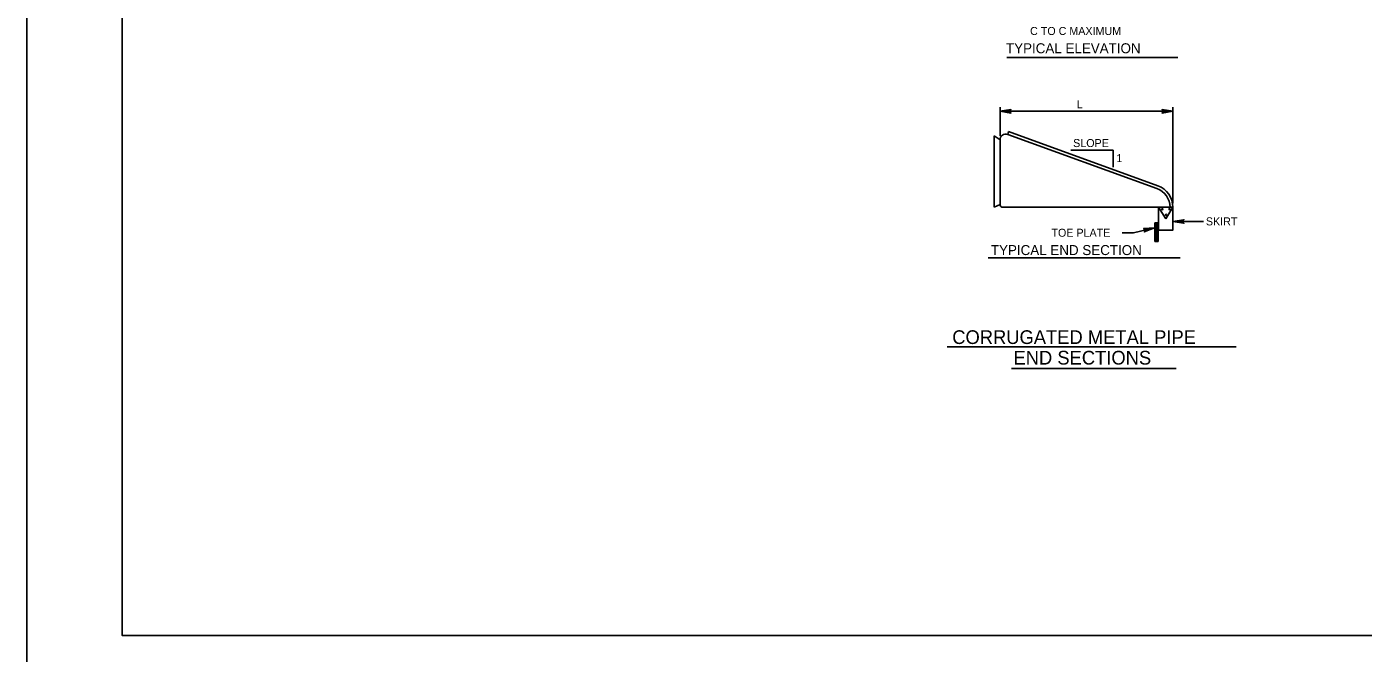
# Model space of a CAD drawing. Extents: x -17 to 888, y -473 to 715.
# Drawn here: x -17 to 544, y 128 to 392 of the extents above; entities that cross this region are included whole.
import ezdxf

# ---------------------------------------------------------------- set-up
doc = ezdxf.new("R2010")
doc.units = 0
for name, color, linetype in [('1', 7, 'Continuous'), ('2', 7, 'Continuous'), ('3', 7, 'Continuous'), ('PLT-BNDY', 7, 'Continuous')]:
    doc.layers.add(name, color=color, linetype=linetype)

msp = doc.modelspace()

# ---------------------------------------------------------------- linework, layer by layer
at = {"layer": '1'}
for p, q in [((456.24, 309.26), (457.69, 309.26)), ((456.24, 308.39), (457.69, 308.39)), ((456.24, 307.46), (457.69, 307.46)), ((456.24, 306.53), (457.69, 306.53)), ((456.24, 305.39), (457.69, 305.39)), ((456.24, 304.46), (457.69, 304.46)), ((456.24, 303.43), (457.69, 303.43)), ((456.24, 302.4), (457.69, 302.4)), ((456.24, 301.47), (457.69, 301.47))]:
    msp.add_line(p, q, dxfattribs=at)
msp.add_lwpolyline([(808.79, 135.89), (808.79, 699.89), (22.79, 699.89), (22.79, 135.89), (808.79, 135.89), (808.79, 162.25), (608.79, 162.25), (608.79, 226.93), (808.79, 226.93), (808.79, 255.89), (608.79, 255.89), (608.79, 135.89), (687.6, 135.89), (687.6, 162.25), (687.6, 135.89), (764.6, 135.89), (764.6, 162.25), (764.6, 149.93), (808.79, 149.93)], dxfattribs=at)
at = {"layer": '2'}
for p, q in [((391.29, 345.86), (391.29, 357.8)), ((436.88, 356.12), (391.29, 356.12)), ((463.87, 356.12), (436.88, 356.12)), ((463.87, 317.48), (463.87, 357.8)), ((388.89, 345.8), (388.89, 315.8)), ((388.89, 345.8), (391.29, 344.18)), ((391.29, 344.18), (391.29, 317)), ((394.92, 347.56), (394.51, 346.43)), ((394.51, 346.43), (457.14, 323.7)), ((394.92, 347.56), (457.55, 324.82)), ((438.84, 339.82), (421.04, 339.82)), ((438.84, 332.62), (438.84, 339.82)), ((388.89, 315.8), (391.29, 317)), ((392.49, 315.8), (462.67, 315.8)), ((457.87, 315.8), (460.87, 311)), ((459.19, 315.01), (459.41, 315.18)), ((459.41, 315.18), (459.19, 314.89)), ((459.19, 314.89), (459.59, 315.02)), ((459.27, 314.81), (459.19, 315.01)), ((459.37, 314.79), (459.26, 315.14)), ((459.26, 315.14), (459.27, 314.81)), ((459.59, 315.02), (459.33, 314.78)), ((459.33, 314.78), (459.56, 314.85)), ((459.42, 314.83), (459.36, 315.18)), ((459.36, 315.18), (459.37, 314.79)), ((459.39, 314.98), (459.39, 314.98)), ((459.44, 315.17), (459.42, 314.83)), ((459.54, 314.89), (459.44, 315.17)), ((459.54, 315.12), (459.54, 314.89)), ((463.87, 315.8), (460.87, 311)), ((462.21, 315.03), (462.43, 315.2)), ((462.43, 315.2), (462.21, 314.9)), ((462.21, 314.9), (462.6, 315.04)), ((462.28, 314.83), (462.21, 315.03)), ((462.38, 314.8), (462.28, 315.15)), ((462.28, 315.15), (462.28, 314.83)), ((462.6, 315.04), (462.34, 314.8)), ((462.34, 314.8), (462.58, 314.87)), ((462.44, 314.84), (462.37, 315.2)), ((462.37, 315.2), (462.38, 314.8)), ((462.4, 315), (462.4, 315)), ((462.46, 315.18), (462.44, 314.84)), ((462.55, 314.91), (462.46, 315.18)), ((462.55, 315.13), (462.55, 314.91)), ((462.67, 315.8), (463.87, 315.8)), ((456.24, 309.26), (456.24, 301.47)), ((456.73, 309.26), (456.73, 301.47)), ((457.28, 309.26), (457.28, 301.47)), ((457.69, 309.26), (457.69, 301.47)), ((460.73, 312.65), (460.95, 312.82)), ((460.95, 312.82), (460.73, 312.52)), ((460.81, 312.45), (460.73, 312.65)), ((460.73, 312.52), (461.12, 312.65)), ((460.91, 312.42), (460.8, 312.77)), ((460.8, 312.77), (460.81, 312.45)), ((461.12, 312.65), (460.87, 312.41)), ((460.87, 312.41), (461.1, 312.49)), ((460.87, 311), (460.87, 311)), ((460.96, 312.46), (460.89, 312.82)), ((460.89, 312.82), (460.91, 312.42)), ((460.91, 312.6), (460.9, 312.64)), ((460.9, 312.64), (460.9, 312.6)), ((460.9, 312.62), (460.92, 312.64)), ((460.92, 312.64), (460.9, 312.61)), ((460.9, 312.6), (460.9, 312.62)), ((460.9, 312.61), (460.94, 312.62)), ((460.92, 312.6), (460.91, 312.64)), ((460.91, 312.64), (460.91, 312.6)), ((460.94, 312.62), (460.91, 312.6)), ((460.91, 312.6), (460.93, 312.61)), ((460.93, 312.61), (460.92, 312.64)), ((460.92, 312.64), (460.92, 312.6)), ((460.92, 312.62), (460.92, 312.62)), ((460.93, 312.63), (460.93, 312.61)), ((460.93, 312.62), (460.93, 312.62)), ((460.98, 312.8), (460.96, 312.46)), ((461.07, 312.52), (460.98, 312.8)), ((461.07, 312.75), (461.07, 312.52))]:
    msp.add_line(p, q, dxfattribs=at)
for points in [[(395.64, 355.57), (395.48, 355.88), (391.29, 356.12), (395.64, 355.57), (395.87, 355.38), (391.29, 356.12), (395.48, 356.32), (395.63, 356.64), (391.29, 356.12), (395.87, 356.84), (395.63, 356.64)], [(459.51, 356.66), (459.67, 356.35), (463.87, 356.12), (459.51, 356.66), (459.29, 356.85), (463.87, 356.12), (459.68, 355.91), (459.52, 355.6), (463.87, 356.12), (459.29, 355.39), (459.52, 355.6)], [(468.23, 309.28), (468.07, 309.6), (463.87, 309.83), (468.23, 309.28), (468.45, 309.09), (463.87, 309.83), (468.06, 310.04), (468.22, 310.35), (463.87, 309.83), (468.45, 310.56), (468.22, 310.35)], [(476.67, 309.83), (463.87, 309.83)], [(442.51, 305.1), (447.31, 305.1), (456.15, 307.16)], [(451.78, 306.7), (452.01, 306.43), (456.15, 307.16), (451.78, 306.7), (451.52, 306.84), (456.15, 307.16), (452.11, 306.01), (452.03, 305.67), (456.15, 307.16), (451.85, 305.41), (452.03, 305.67)]]:
    msp.add_lwpolyline(points, dxfattribs=at)
msp.add_lwpolyline([(463.87, 315.8), (463.87, 306.2), (457.87, 306.2), (457.87, 315.8)], close=True, dxfattribs=at)
for centre, radius in [((459.39, 314.98), 0.24), ((462.4, 315), 0.24), ((460.93, 312.62), 0.24), ((460.92, 312.62), 0.024)]:
    msp.add_circle(centre, radius, dxfattribs=at)
for centre, radius, start, end in [((393.69, 344.18), 2.4, 70.0483, 180), ((454.27, 315.8), 8.4, 0, 70.0484), ((454.27, 315.8), 9.6, 0, 70.0484), ((392.49, 317), 1.2, 180, 270)]:
    msp.add_arc(centre, radius, start, end, dxfattribs=at)
at = {"layer": '3'}
for p, q in [((394.11, 378.73), (465.99, 378.73)), ((386.37, 294.52), (466.85, 294.52)), ((369.14, 257.19), (490.41, 257.19)), ((396.05, 248.04), (465.16, 248.04))]:
    msp.add_line(p, q, dxfattribs=at)
at = {"layer": 'PLT-BNDY'}
msp.add_lwpolyline([(-17.21, 714.89), (823.79, 714.89), (823.79, 120.89), (-17.21, 120.89)], close=True, dxfattribs=at)

# ---------------------------------------------------------------- texts
at = {"layer": '3'}
for s, height, p in [('C TO C MAXIMUM', 3.36, (403.92, 388.18)), ('TYPICAL ELEVATION', 4.2, (393.8, 380.5)), ('L', 3.36, (423.46, 357.38)), ('SLOPE', 3.36, (421.99, 341.09)), ('1', 3.36, (440.13, 334.75)), ('SKIRT', 3.36, (477.7, 308.18)), ('TOE PLATE', 3.36, (412.88, 303.41)), ('TYPICAL END SECTION', 4.2, (387.46, 295.71)), ('CORRUGATED METAL PIPE', 5.76, (371.24, 258.35)), ('END SECTIONS', 5.76, (396.95, 249.71))]:
    msp.add_text(s, height=height, dxfattribs=at).set_placement(p)

doc.saveas('drawing.dxf')
